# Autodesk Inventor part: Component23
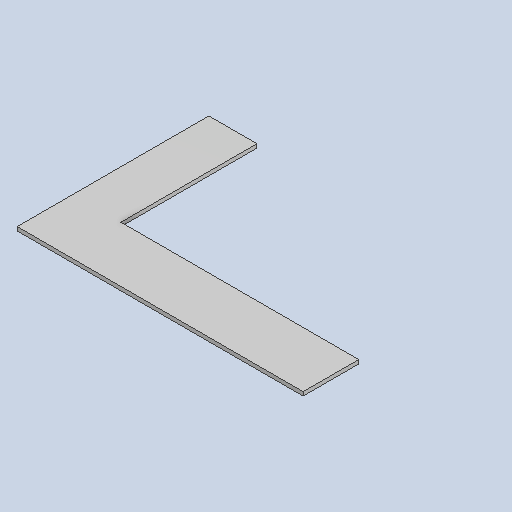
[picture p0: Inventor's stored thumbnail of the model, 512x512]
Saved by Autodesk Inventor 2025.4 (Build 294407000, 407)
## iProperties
Created: 2026-06
Part Number: Component23
Material: Generic
Document SubType Name: Modeling
Designer: AdminForWorker
Density: 1 g/cm^3
Appearance: Default
Title: Component23
Author: AdminForWorker
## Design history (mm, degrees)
feature "Body1"
body "Solid1"
